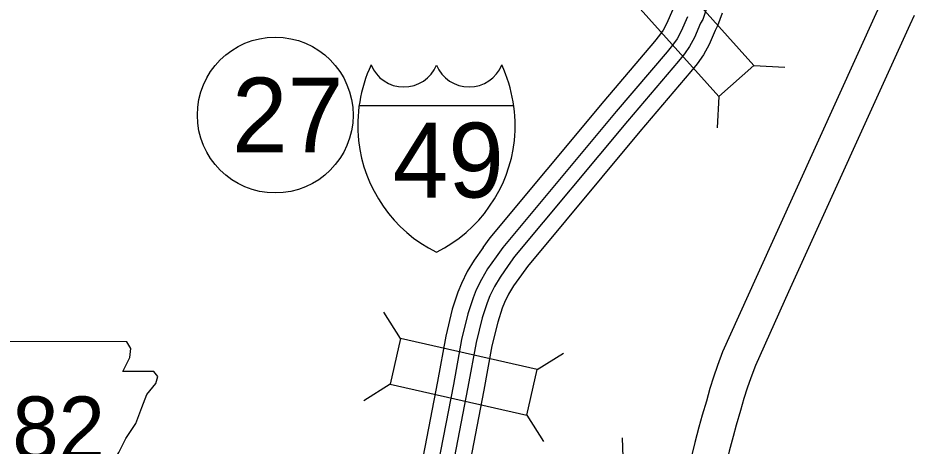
# Model space of a CAD drawing. Extents: x -939622 to -934245, y 1383184 to 1385301.
# Drawn here: x -936348.95 to -936326.17, y 1384717.7 to 1384728.57 of the extents above; entities that cross this region are included whole.
import ezdxf

# ---------------------------------------------------------------- set-up
doc = ezdxf.new("R2010")
doc.units = 0
for name, color, linetype in [('Level 15', 7, 'Continuous'), ('Level 19', 7, 'Continuous'), ('Level 20', 7, 'Continuous'), ('Level 21', 7, 'Continuous'), ('Level 23', 7, 'Continuous'), ('Level 27', 7, 'Continuous')]:
    doc.layers.add(name, color=color, linetype=linetype)

msp = doc.modelspace()

# ---------------------------------------------------------------- linework, layer by layer
at = {"layer": 'Level 15'}
for points in [[(-936327.096, 1384728.766), (-936330.184, 1384721.982), (-936331.036, 1384720.088), (-936331.167, 1384719.741), (-936331.27, 1384719.448), (-936331.361, 1384719.156), (-936331.447, 1384718.839), (-936331.552, 1384718.477), (-936331.64, 1384718.174), (-936331.741, 1384717.786), (-936331.845, 1384717.369), (-936331.9, 1384717.066), (-936331.97, 1384716.711), (-936332.007, 1384716.514), (-936332.022, 1384716.359), (-936332.023, 1384716.207), (-936332.017, 1384715.962)], [(-936326.169, 1384728.634), (-936326.276, 1384728.396), (-936329.364, 1384721.611), (-936330.204, 1384719.744), (-936330.321, 1384719.433), (-936330.415, 1384719.166), (-936330.496, 1384718.904), (-936330.581, 1384718.595), (-936330.688, 1384718.227), (-936330.772, 1384717.935), (-936330.869, 1384717.564), (-936330.965, 1384717.18), (-936331.016, 1384716.9), (-936331.086, 1384716.539), (-936331.115, 1384716.387), (-936331.122, 1384716.314), (-936331.123, 1384716.214), (-936331.117, 1384715.985)]]:
    msp.add_lwpolyline(points, dxfattribs=at)
at = {"layer": 'Level 19'}
for points in [[(-936332.303, 1384728.783), (-936332.461, 1384728.42), (-936332.547, 1384728.262), (-936332.638, 1384728.132), (-936332.764, 1384727.976), (-936334.059, 1384726.459), (-936336.952, 1384722.99), (-936337.129, 1384722.738)], [(-936331.932, 1384728.602), (-936332.09, 1384728.239), (-936332.195, 1384728.045), (-936332.309, 1384727.883), (-936332.447, 1384727.713), (-936333.744, 1384726.193), (-936336.624, 1384722.739), (-936336.792, 1384722.501)], [(-936331.448, 1384728.811), (-936331.542, 1384728.534), (-936331.595, 1384728.437), (-936331.753, 1384728.075), (-936331.876, 1384727.848), (-936332.009, 1384727.658), (-936332.159, 1384727.473), (-936333.457, 1384725.951), (-936336.327, 1384722.51), (-936336.485, 1384722.285)], [(-936331.051, 1384728.695), (-936331.163, 1384728.368), (-936331.224, 1384728.256), (-936331.382, 1384727.894), (-936331.524, 1384727.631), (-936331.679, 1384727.409), (-936331.842, 1384727.209), (-936333.142, 1384725.685), (-936335.999, 1384722.259), (-936336.148, 1384722.047)], [(-936337.127, 1384722.741), (-936337.355, 1384722.422), (-936337.532, 1384722.127), (-936337.677, 1384721.829), (-936337.766, 1384721.605), (-936337.907, 1384721.171), (-936338.076, 1384720.489), (-936338.284, 1384719.336), (-936338.932, 1384715.997)], [(-936336.791, 1384722.502), (-936337.01, 1384722.196), (-936337.169, 1384721.93), (-936337.299, 1384721.662), (-936337.378, 1384721.465), (-936337.51, 1384721.058), (-936337.672, 1384720.403), (-936337.879, 1384719.26), (-936338.527, 1384715.918)], [(-936336.486, 1384722.284), (-936336.695, 1384721.99), (-936336.839, 1384721.751), (-936336.956, 1384721.51), (-936337.025, 1384721.338), (-936337.149, 1384720.955), (-936337.305, 1384720.324), (-936337.51, 1384719.191), (-936338.158, 1384715.847)], [(-936336.15, 1384722.044), (-936336.35, 1384721.764), (-936336.476, 1384721.554), (-936336.579, 1384721.343), (-936336.637, 1384721.198), (-936336.752, 1384720.841), (-936336.902, 1384720.238), (-936337.105, 1384719.115), (-936337.754, 1384715.768)]]:
    msp.add_lwpolyline(points, dxfattribs=at)
at = {"layer": 'Level 20'}
for p, q in [((-936330.244, 1384727.366), (-936329.453, 1384727.323)), ((-936331.129, 1384726.573), (-936331.172, 1384725.783)), ((-936339.227, 1384720.426), (-936339.649, 1384721.096)), ((-936335.751, 1384719.637), (-936335.081, 1384720.06)), ((-936339.49, 1384719.268), (-936340.16, 1384718.846)), ((-936336.014, 1384718.479), (-936335.592, 1384717.809)), ((-936333.553, 1384717.117), (-936333.579, 1384717.908))]:
    msp.add_line(p, q, dxfattribs=at)
for points in [[(-936333.507, 1384729.227), (-936331.129, 1384726.573), (-936330.244, 1384727.366), (-936332.623, 1384730.02)], [(-936339.49, 1384719.268), (-936336.014, 1384718.479), (-936335.751, 1384719.637), (-936339.227, 1384720.426)]]:
    msp.add_lwpolyline(points, close=True, dxfattribs=at)
at = {"layer": 'Level 21'}
msp.add_lwpolyline([(-936350.746, 1384720.349), (-936350.518, 1384718.826), (-936350.619, 1384716.517), (-936350.416, 1384716.39), (-936350.036, 1384716.39), (-936350.036, 1384715.578), (-936346.838, 1384715.578), (-936346.686, 1384715.908), (-936346.737, 1384716.441), (-936346.661, 1384717.05), (-936346.381, 1384717.532), (-936346.204, 1384717.887), (-936345.95, 1384718.268), (-936345.798, 1384718.674), (-936345.671, 1384719.004), (-936345.442, 1384719.283), (-936345.392, 1384719.461), (-936345.493, 1384719.588), (-936346.28, 1384719.588), (-936346.102, 1384719.943), (-936346.077, 1384720.171), (-936346.182, 1384720.347)], close=True, dxfattribs=at)
at = {"layer": 'Level 23'}
msp.add_line((-936340.277, 1384726.344), (-936336.344, 1384726.344), dxfattribs=at)
for centre, radius, start, end in [((-936336.622, 1384725.832), 3.69, 155.2204, 185.7928), ((-936339.14, 1384727.718), 0.899, 202.1459, 337.3414), ((-936337.481, 1384727.718), 0.899, 202.6586, 337.8541), ((-936339.999, 1384725.832), 3.69, 354.2072, 24.7796), ((-936336.69, 1384725.863), 3.626, 186.3923, 243.4571), ((-936339.931, 1384725.863), 3.626, 296.5429, 353.6077)]:
    msp.add_arc(centre, radius, start, end, dxfattribs=at)
at = {"layer": 'Level 27'}
msp.add_circle((-936342.409, 1384726.105), 1.98, dxfattribs=at)

# ---------------------------------------------------------------- texts
at = {"layer": 'Level 21'}
msp.add_text('282', height=1.584, dxfattribs=at).set_placement((-936350.271, 1384717.371))
at = {"layer": 'Level 23'}
msp.add_text('49', height=1.9008, dxfattribs=at).set_placement((-936339.424, 1384724.01))
at = {"layer": 'Level 27'}
msp.add_text('27', height=1.9008, dxfattribs=at).set_placement((-936343.508, 1384725.155))

doc.saveas('drawing.dxf')
